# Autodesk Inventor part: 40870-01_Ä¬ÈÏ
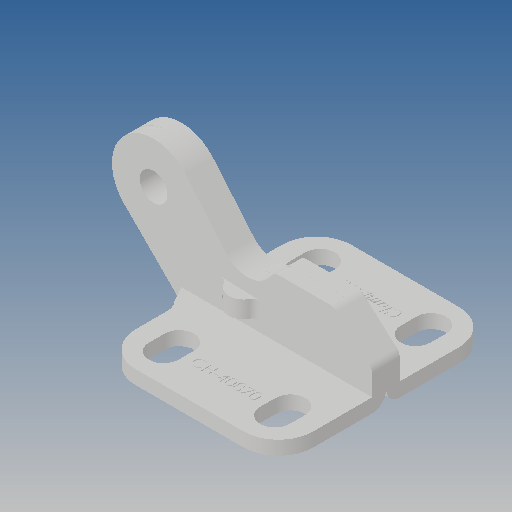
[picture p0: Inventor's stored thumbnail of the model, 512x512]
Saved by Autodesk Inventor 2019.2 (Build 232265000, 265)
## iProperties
Created: 2010-06
Part Number: 40870-01_Ä¬ÈÏ
Material: Ogólny
Document SubType Name: Modeling
Designer: CADENGINEERING4
Density: 1 g/cm^3
Appearance: Domyślna
Author: CADENGINEERING4
Revision Number: ÈÎºÎ
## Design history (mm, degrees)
feature "NONE"
feature "NONE:1"
node "Bryła1"
node "Bryła2"
